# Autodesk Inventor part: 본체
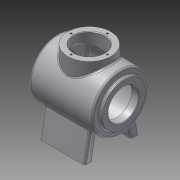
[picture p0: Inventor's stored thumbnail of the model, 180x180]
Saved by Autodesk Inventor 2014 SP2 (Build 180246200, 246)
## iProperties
Created: 2015-01
Part Number: 본체
Material: 알루미늄 6061
Document SubType Name: 판금
Designer: 201-06
Mass: 1021.13 g
Surface Area: 1060.37 cm^2
Volume: 376.8 cm^3
Density: 2.71 g/cm^3
Appearance: 알루미늄 - 평지
Sheet Metal Rule: 기본값
Author: 201-06
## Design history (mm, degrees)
sketch "스케치1"
  geometry: C1 r 50 at (0, 0); 1 further point
  constraints: 1 centre point, 1 coincident
  dimensions: "d0" = 100 diameter of C1
extrude "돌출1" new body sketch "스케치1" distance "d1" = 112; taper "d2" = 0 deg
sketch "스케치2"
  geometry: C1 r 38 at (0, 0); 1 further point
  constraints: 1 centre point, 1 coincident
  dimensions: "d3" = 76 diameter of C1
extrude "돌출2" join sketch "스케치2" distance "d4" = 5; taper "d5" = 0 deg
sketch "스케치3"
  geometry: C1 r 38 at (0, 0); 1 further point
  constraints: 1 centre point, 1 coincident
  dimensions: "d6" = 76 diameter of C1
extrude "돌출3" join sketch "스케치3" distance "d7" = 5; taper "d8" = 0 deg
node "작업 평면1"
sketch "스케치4"
  geometry: L1 (48, -80)-(34, -80); L2 (34, -80)-(26.356, -36.65); L3 (48, -80)-(38.427, -25.71); L4 (48, -80)-(103.128, -80); L5 (38.427, -25.71)-(26.356, -36.65); 1 further point
  constraints: 10 end point, 2 horizontal, 1 equal length
  dimensions: "d10" = 80 vertical distance of L1.start point (0, 0); "d11" = 48 horizontal distance of point (0, 0) L1.start; "d12" = 14 distance of L1.start L1.end; "d13" = 100 deg angle of L1 L2; "d14" = 100 deg angle of L4 L3; "d15" = 42.1866 deg angle of L5 L4; "d16" = 44.85549 distance from line of point (0, 0) L5
extrude "돌출4" join sketch "스케치4" stored distance "d17" = 80; taper "d18" = 0 deg
node "작업 평면2"
sketch "스케치5"
  geometry: L1 (16, -27.282)-(16, -39.336) reference; L2 (16, -39.336)-(96, -39.336) reference; L3 (96, -39.336)-(96, -27.282) reference; L4 (96, -27.282)-(16, -27.282) reference; L5 (16, 39.336)-(16, 27.282) reference; L6 (16, 27.282)-(96, 27.282) reference; L7 (96, 27.282)-(96, 39.336) reference; L8 (96, 39.336)-(16, 39.336) reference; L9 (112, -50)-(112, 50) reference; L10 (0, 50)-(0, -50) reference; C1 r 38 at (56, 0); 1 further point
  constraints: 1 centre point
  dimensions: "d20" = 76 diameter of C1; "d21" = 56 distance from line of C1.centre L9; "d22" = 39.33621 distance from line of C1.centre L8
extrude "돌출5" join sketch "스케치5" distance "d23" = 62; taper "d24" = 0 deg
sketch "스케치6"
  geometry: C1 r 27 at (0, 0); 1 further point
  constraints: 1 centre point, 1 coincident
  dimensions: "d25" = 54 diameter of C1
extrude "돌출6" cut sketch "스케치6" distance "d26" = 13; taper "d27" = 0 deg
sketch "스케치7"
  geometry: C1 r 45 at (0, 0); 1 further point
  constraints: 1 centre point, 1 coincident
  dimensions: "d28" = 90 diameter of C1
extrude "돌출7" cut sketch "스케치7" distance "d29" = 97; taper "d30" = 0 deg
sketch "스케치8"
  geometry: C1 r 27 at (0, 0); 1 further point
  constraints: 1 centre point, 1 coincident
  dimensions: "d31" = 54 diameter of C1
extrude "돌출8" cut sketch "스케치8" distance "d32" = 12; taper "d33" = 0 deg
sketch "스케치10"
  geometry: C1 r 27 at (0, 0); 1 further point
  constraints: 1 centre point, 1 horizontal alignment
  dimensions: "d34" = 54 diameter of C1; "d35" = 56 distance of point (-56, 0) C1.centre
extrude "돌출9" cut sketch "스케치10" distance "d36" = 42; taper "d37" = 0 deg
sketch "스케치11" dims "d38" = 64
  geometry: 6 further points
  constraints: 2 horizontal alignment, 1 coincident, 7 other
  dimensions: "d41" = 360 deg dimension on point (0, 0) point (32, 0) (derived)
hole "구멍1" sketch "스케치11" at (32, 0), (0, 32), (-32, 0), (0, -32) diameter "d43" = 3.242; stored, may be unused: countersink angle "d47" = 90 deg, drill point angle "d49" = 118 deg; dims "d44" = 8, "d45" = 4, "d46" = 2, "d48" = 10
sketch "스케치12" dims "d50" = 64
  geometry: 9 further points
  constraints: 3 horizontal alignment, 2 coincident, 2 vertical alignment, 19 other
  dimensions: "d51" = 88 distance of point (32, 0) point (-56, 0); "d52" = 56 distance of point (0, 0) point (-56, 0); "d55" = 360 deg dimension on point (0, 0) point (32, 0) (derived)
hole "구멍2" sketch "스케치12" at (32, 0), (0, 32), (-32, 0), (0, -32) diameter "d57" = 3.242; stored, may be unused: countersink angle "d61" = 90 deg, drill point angle "d63" = 118 deg; dims "d58" = 8, "d59" = 4, "d60" = 2, "d62" = 10
node "작업 평면3"
chamfer "모따기1" distance "d74" = 1; stored, may be unused: second distance "d75" = 2, angle "d76" = 45 deg
fillet "모깎기1" dims "d77" = 3
fillet "모깎기2" dims "d78" = 3
fillet "모깎기3" dims "d79" = 3
fillet "모깎기4" dims "d80" = 3
fillet "모깎기5" dims "d81" = 3
node "작업 평면4"
sketch "스케치15"
  geometry: L1 (-82, 6)-(-28, 6); L2 (-28, 6)-(-28, -6); L3 (-28, -6)-(-82, -6); L4 (-82, -6)-(-82, 6); L5 (-55, 6)-(-55, -6); L6 (-117, 38)-(-117, -38) reference; 2 further points
  constraints: 10 end point, 3 midpoint, 2 parallel, 1 horizontal, 1 horizontal alignment, 1 perpendicular
  dimensions: "d83" = 54 distance of L2.end L3.end; "d84" = 12 distance of L1.end L2.end; "d85" = 62 distance between parallel lines of L6 L5
extrude "돌출10" join sketch "스케치15" distance "d86" = 7; taper "d87" = 0 deg
sketch "스케치16"
  geometry: L1 (-28, 6)-(-82, 6) reference; L2 (-82, 6)-(-82, -6) reference; L3 (-82, -6)-(-28, -6) reference; L4 (-28, -6)-(-28, 6) reference; 4 further points
  constraints: 2 midpoint, 1 horizontal alignment, 1 vertical alignment, 1 other
feature "엠보싱3" sketch "스케치16" dims "d1" = 112, "d88" = 0.5, "d89" = 0
node "솔리드1"
mirror "대칭1"
mirror "대칭2"
node "투영된 루프1"
node "투영된 루프3"
other parameters: "d9" = 56, "d19" = 0, "K계수" = 4.4, "BendRadius" = 0.5 (derived), "BendReliefWidth" = 0.5 (derived), "BendReliefDepth" = 0.25 (derived), "CornerReliefSize" = 2 (derived), "SeamGap" = 0.01, "MinimumRemnant" = 1 (derived), "TransitionRadius" = 0.5 (= BendRadius), "d64" = 130.5, "d82" = 45
